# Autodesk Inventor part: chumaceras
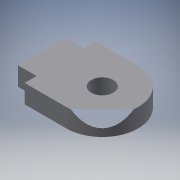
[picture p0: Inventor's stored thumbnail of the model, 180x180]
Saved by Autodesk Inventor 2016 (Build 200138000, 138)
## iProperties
Created: 2017-06
Part Number: chumaceras
Material: Generic
Document SubType Name: Modeling
Designer: laboratorioesan
Density: 1 g/cm^3
Appearance: Default
Author: laboratorioesan
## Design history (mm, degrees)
sketch "Sketch1"
  geometry: L1 (0, 0)-(0, 40) reference; L2 (0, 0)-(15.5, 0) reference; L3 (15.5, 40)-(15.5, 0) reference; L4 (0, 40)-(15.5, 40) reference; L5 (15.5, 120)-(15.5, -80) reference; L6 (15.5, -10)-(50.5, -10); L7 (15.5, 50)-(50.5, 50); C1 r 15 at (50.5, 20) reference; C2 r 15 at (50.5, 20) reference; A1 r 30 centre (50.5, 20) between (50.5, -10) and (50.5, 50)
  constraints: 4 end point, 2 horizontal, 2 point on circle, 2 point on line, 1 centre point, 1 coincident, 1 tangent
  dimensions: "d0" = 60 diameter of A1
extrude "Extrusion1" new body sketch "Sketch1" distance "d1" = 15.5; taper "d2" = 0 deg
sketch "Sketch2"
  geometry: C1 r 15 at (50.5, 20) reference; C2 r 9.25 at (50.5, 20); 1 further point
  constraints: 1 centre point, 1 coincident
  dimensions: "d3" = 18.5 diameter of C2
extrude "Extrusion2" join sketch "Sketch2" distance "d4" = 15.5; taper "d5" = 0 deg
body "Solid1"
node "Reference1"
node "Reference2"
node "Reference3"
node "Reference4"
